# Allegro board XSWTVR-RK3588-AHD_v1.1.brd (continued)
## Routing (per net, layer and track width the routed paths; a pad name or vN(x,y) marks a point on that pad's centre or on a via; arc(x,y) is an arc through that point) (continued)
GMAC1_MDC: length 49.5
  TOP w0.127: v1(112.04,67.83) 112.03,67.84 111.63,67.84 U1.153 ; v1(129.87,77.59) 131.48,77.59 135.1,81.21 135.1,84.49 140.54,89.93 143.28,89.93 143.73,89.48 U19.13
  BOTTOM w0.127: v1(112.04,67.83) 112.04,73.21 113.01,74.18 126.46,74.18 v1(129.87,77.59)
GMAC1_MDIO: length 50.1
  TOP w0.127: U1.152 v1(112.81,66.84) ; U19.14 143.31,89.07 R220.2 142.54,88.87 139.96,88.87 135.45,84.36 135.45,80.98 v1(132.12,77.64)
  BOTTOM w0.127: v1(132.12,77.64) 130.96,77.64 126.75,73.43 113.27,73.43 112.81,72.97 v1(112.81,66.84)
GMAC1_RSTN_L: length 51
  TOP w0.127: R221.1 140.69,90.48 134.77,84.56 134.77,81.37 131.36,77.95 v1(130.76,77.95) ; U1.148 v1(112.44,62.84)
  BOTTOM w0.127: v1(130.76,77.95) 126.6,73.8 113.11,73.8 112.44,73.13 v1(112.44,62.84)
GMAC1_RXCLK: length 43.5
  TOP w0.127: 148.36,79.57 148.19,79.4 v1(146.93,79.4) ; 148.36,79.57 R226.2 ; 148.36,79.57 C304.1 ; v1(113.39,72.56) 112.11,73.84 U1.159
  BOTTOM w0.127: v1(146.93,79.4) 146.93,77.68 146.15,76.89 145.04,76.89 144.86,76.71 131.17,76.71 127.01,72.56 v1(113.39,72.56)
GMAC1_RXD0: length 39.1
  TOP w0.127: v1(146.03,77.38) 146.25,77.59 R222.2 ; U1.160 111.86,74.84 112.71,73.99 112.71,73.99 113.27,73.43 113.27,73.21 v1(113.43,73.06)
  BOTTOM w0.127: v1(113.43,73.06) 126.95,73.06 131.05,77.16 144.68,77.16 144.9,77.38 v1(146.03,77.38)
GMAC1_RXD1: length 39.1
  TOP w0.127: U1.157 112.72,71.84 v1(113.21,71.34) ; R223.2 v1(145.19,76.52)
  BOTTOM w0.127: v1(113.21,71.34) 113.21,71.95 113.45,72.19 127.26,72.19 131.33,76.26 144.93,76.26 v1(145.19,76.52)
GMAC1_RXD2: length 39.1
  TOP w0.127: v1(139.13,77.53) 139.16,77.5 143.53,77.5 R224.2 ; v1(112.75,84.24) 111.15,85.84 U1.171
  BOTTOM w0.127: v1(112.75,84.24) 112.75,81.54 115.93,78.35 125.67,78.35 125.69,78.34 132.67,78.34 133.48,77.53 v1(139.13,77.53)
GMAC1_RXD3: length 40.6
  TOP w0.127: U1.174 111.64,88.84 112.74,87.73 v1(112.74,84.77) ; v1(139.68,77.89) 142.87,77.89 R225.2
  BOTTOM w0.127: v1(139.68,77.89) 133.64,77.89 132.8,78.74 116.24,78.74 113.14,81.84 113.14,84.37 v1(112.74,84.77)
GMAC1_RXDV_CRS: length 42.8
  TOP w0.127: R227.2 v1(147.3,79.91) ; v1(113.59,71.81) 112.56,72.84 U1.158
  BOTTOM w0.127: v1(113.59,71.81) 127.53,71.81 131.5,75.78 145.52,75.78 147.3,77.57 v1(147.3,79.91)
GMAC1_TXCLK: length 55.3
  TOP w0.127: U1.161 111.67,75.84 112.98,74.53 118.63,74.53 119.4,75.3 132.91,75.3 133.83,76.22 134.01,76.22 134.61,75.61 134.79,75.61 134.97,75.79 134.97,75.97 134.37,76.57 134.37,76.75 134.55,76.93 134.73,76.93 135.33,76.33 135.51,76.33 135.69,76.51 135.69,76.69 135.08,77.29 135.08,77.47 135.26,77.65 135.44,77.65 136.05,77.04 136.23,77.04 136.41,77.22 136.41,77.4 135.8,78.01 135.8,78.19 135.98,78.37 136.16,78.37 136.77,77.76 136.95,77.76 137.13,77.94 137.13,78.12 136.52,78.73 136.52,78.91 136.7,79.09 136.88,79.09 137.49,78.48 137.67,78.48 137.85,78.66 137.85,78.84 137.24,79.45 137.24,79.63 137.55,79.94 137.55,81.38 138.06,81.9 138.24,81.9 138.45,81.68 138.63,81.68 138.81,81.86 138.81,82.04 138.6,82.26 138.6,82.44 138.78,82.62 138.96,82.62 139.17,82.4 139.35,82.4 139.53,82.58 139.53,82.76 139.32,82.97 139.32,83.15 139.5,83.33 139.68,83.33 139.89,83.12 140.07,83.12 140.25,83.3 140.25,83.48 140.04,83.69 140.04,83.87 140.22,84.05 140.4,84.05 140.61,83.84 140.79,83.84 140.97,84.02 140.97,84.2 140.75,84.41 140.75,84.59 140.93,84.77 141.11,84.77 141.33,84.56 141.51,84.56 141.69,84.74 141.69,84.92 141.47,85.13 141.47,85.31 C297.1 U19.20
GMAC1_TXD0: length 52.8
  TOP w0.127: v1(114.6,74.91) 117.86,74.91 118.83,75.88 132.46,75.88 136.85,80.28 136.85,82.54 137.64,83.33 137.82,83.33 137.97,83.18 138.15,83.18 138.33,83.36 138.33,83.54 138.18,83.69 138.18,83.87 138.36,84.05 138.54,84.05 138.69,83.9 138.87,83.9 139.05,84.08 139.05,84.26 138.9,84.41 138.9,84.59 139.08,84.77 139.26,84.77 139.41,84.62 139.59,84.62 139.76,84.8 139.76,84.98 139.62,85.13 139.62,85.31 139.8,85.49 139.98,85.49 140.12,85.34 140.3,85.34 140.48,85.52 140.48,85.7 140.34,85.85 140.34,86.03 141.78,87.47 U19.18 ; v1(111.67,65.84) 111.44,65.84 U1.151
  BOTTOM w0.127: v1(114.6,74.91) 112.75,74.91 111.36,73.53 111.36,66.14 v1(111.67,65.84)
GMAC1_TXD1: length 55
  TOP w0.127: v1(114.17,75.28) 117.67,75.28 118.59,76.21 132.31,76.21 136.54,80.44 136.54,82.62 141.8,87.87 U19.17 ; U1.147 111.44,61.84 v1(111.67,61.84)
  BOTTOM w0.127: v1(111.67,61.84) 111.67,65.19 111.02,65.84 111.02,73.72 112.58,75.28 v1(114.17,75.28)
GMAC1_TXD2: length 52.9
  TOP w0.127: U19.16 141.78,88.27 141.34,87.84 141.16,87.84 141,88 140.82,88 140.64,87.82 140.64,87.65 140.8,87.48 140.8,87.3 140.62,87.12 140.44,87.12 140.28,87.29 140.1,87.29 139.92,87.11 139.92,86.93 140.09,86.76 140.09,86.58 139.91,86.4 139.73,86.4 139.56,86.57 139.38,86.57 139.2,86.39 139.2,86.21 139.37,86.04 139.37,85.86 139.19,85.68 139.01,85.68 138.84,85.85 138.66,85.85 138.48,85.67 138.48,85.49 138.65,85.32 138.65,85.14 138.47,84.97 138.29,84.97 138.12,85.13 137.94,85.13 137.76,84.95 137.76,84.77 137.93,84.61 137.93,84.43 137.75,84.25 137.57,84.25 137.41,84.41 137.23,84.41 137.05,84.23 137.05,84.05 137.21,83.89 137.21,83.71 136.19,82.69 136.19,80.68 132.27,76.76 127.72,76.76 v1(127.63,76.85) ; v1(112.35,85.65) 112.35,87 111.51,87.84 U1.173
  BOTTOM w0.127: v1(127.63,76.85) 127.26,77.22 116.63,77.22 112.35,81.5 v1(112.35,85.65)
GMAC1_TXD3: length 52.5
  TOP w0.127: v1(126.91,76.83) 127.3,77.22 127.47,77.22 132.22,77.22 135.78,80.78 135.78,83.44 136.37,84.03 136.37,84.21 136.21,84.37 136.21,84.55 136.39,84.73 136.57,84.73 136.73,84.57 136.91,84.57 137.09,84.75 137.09,84.93 136.93,85.09 136.93,85.27 137.11,85.44 137.28,85.44 137.44,85.28 137.62,85.28 137.8,85.46 137.8,85.64 137.64,85.8 137.64,85.98 137.82,86.16 138,86.16 138.16,86 138.34,86 138.52,86.18 138.52,86.36 138.36,86.52 138.36,86.7 138.54,86.88 138.72,86.88 138.88,86.72 139.06,86.72 139.24,86.9 139.24,87.08 139.08,87.24 139.08,87.42 139.26,87.6 139.44,87.6 139.6,87.44 139.78,87.44 139.96,87.62 139.96,87.8 139.8,87.96 139.8,88.14 139.98,88.32 140.16,88.32 140.32,88.16 140.5,88.16 140.94,88.6 145.38,88.6 U19.15 ; v1(111.98,86.01) 111.98,86.06 111.98,86.06 111.98,86.17 111.31,86.84 U1.172
  BOTTOM w0.127: v1(126.91,76.83) 116.56,76.83 111.98,81.41 v1(111.98,86.01)
GMAC1_TXEN: length 58.8
  TOP w0.127: v1(111.67,56.84) 111.44,56.84 U1.142 ; U19.19 142.03,87.07 140.86,85.9 140.86,85.53 137.16,81.84 137.16,80.08 132.68,75.59 119.12,75.59 118.74,75.21 118.73,75.21 v1(118.47,74.95)
  BOTTOM w0.127: v1(111.67,56.84) 112.03,57.2 112.03,66.18 111.67,66.55 111.67,73.35 112.86,74.55 114.95,74.55 115.36,74.95 v1(118.47,74.95)
GNSS_ANT: length 10
  TOP w0.559: J18.1 80.13,151.41 arc(80.28,150.66) 80.7,150.03 arc(81.35,149.06) 81.58,147.91 L5.1 81.58,143.51 U15.11
GNSS_RST: length 135.2
  TOP w0.127: J24.15 100.89,38.45 101.12,38.68 v1(101.12,39.53) ; U15.8 84.87,144.05 86.19,145.37 92.54,145.37 92.93,144.98 97.08,144.98 97.82,144.23 97.82,114.29 99.22,112.9 102.61,112.9 v1(103.54,111.96)
  L3 w0.127: v1(106.2,104.56) 106.2,106.04 103.54,108.69 v1(103.54,111.96)
  BOTTOM w0.127: v1(106.2,104.56) 106.2,63.38 109.29,60.28 109.29,42.32 107.48,40.5 105.14,40.5 104.17,39.53 v1(101.12,39.53)
GNSS_STATE: length 122.4
  TOP w0.127: v1(104.1,111.96) 102.76,113.3 99.34,113.3 98.23,114.41 98.23,146.55 97.3,147.48 R135.1 ; J24.7 104.89,39.1 104.88,39.1 v1(104.88,39.47)
  L3 w0.127: v1(106.61,103.87) 106.61,106.17 104.1,108.68 v1(104.1,111.96)
  BOTTOM w0.127: v1(106.61,103.87) 106.61,63.57 109.72,60.46 109.72,42.08 107.8,40.16 105.57,40.16 v1(104.88,39.47)
HDMI0_EARC+: length 10.2
  TOP w0.127: J17.14 14.06,88.75 14.07,88.76 ED8.1 14.51,89.05 14.76,89.3 16.02,89.3 16.5,89.77 16.5,90.22 18.04,91.76 C245.2
HDMI0_EARC-: length 12
  TOP w0.127: J17.19 9.54,91.24 13.79,91.24 ED4.1 14.51,92 16.32,93.8 C246.2 16.96,96.99 R121.2
HDMI0_TX0N_PORT: length 8.5
  TOP w0.127: J17.9 9.54,86.24 10.79,86.24 11.17,85.86 12.79,85.86 13.54,85.11 14.1,85.11 14.2,85.21 ED3.9 ED3.2 15.91,85.21 16.01,85.11 17.14,85.11 C240.2
HDMI0_TX0N_PORT/EDP0_TX_D0N: length 30.2
  TOP w0.127: C240.1 18.25,85.36 18.48,85.13 34.72,85.13 41.08,91.49 44.1,91.49 44.45,91.84 U1.16
HDMI0_TX0P_PORT: length 8.5
  TOP w0.127: J17.7 9.54,85.24 10.31,85.24 10.76,85.24 11.08,85.56 12.67,85.56 13.41,84.81 14.12,84.81 14.21,84.71 ED3.10 ED3.1 15.91,84.71 16.01,84.81 17.17,84.81 C239.2
HDMI0_TX0P_PORT/EDP0_TX_D0P: length 30.2
  TOP w0.127: U1.17 44.46,90.84 44.11,91.18 41.21,91.18 34.85,84.82 18.48,84.82 18.25,84.59 C239.1
HDMI0_TX1N_PORT: length 8.5
  TOP w0.127: C238.2 17.17,83.62 15.71,83.62 15.61,83.71 ED2.5 ED2.6 14.22,83.71 14.12,83.62 13.33,83.62 12.56,84.39 11.13,84.39 10.79,84.74 9.54,84.74 J17.6
HDMI0_TX1N_PORT/EDP0_TX_D1N: length 30.6
  TOP w0.127: U1.18 44.56,89.84 44.21,89.49 41.24,89.49 35.36,83.6 28.07,83.6 27.81,83.86 27.18,83.86 26.92,83.6 26.45,83.6 26.19,83.86 25.55,83.86 25.3,83.6 24.82,83.6 24.56,83.86 23.93,83.86 23.67,83.6 18.48,83.6 18.25,83.83 C238.1
HDMI0_TX1P_PORT: length 8.5
  TOP w0.127: C237.2 17.14,83.31 15.71,83.31 15.61,83.21 ED2.4 ED2.7 14.24,83.21 14.15,83.31 13.21,83.31 12.43,84.09 11.14,84.09 10.79,83.74 9.54,83.74 J17.4
HDMI0_TX1P_PORT/EDP0_TX_D1P: length 30.6
  TOP w0.127: U1.19 44.59,88.84 44.24,89.18 41.37,89.18 35.48,83.3 27.95,83.3 27.69,83.56 27.31,83.56 27.05,83.3 26.32,83.3 26.06,83.56 25.68,83.56 25.42,83.3 24.7,83.3 24.44,83.56 24.06,83.56 23.8,83.3 18.48,83.3 18.25,83.07 C237.1
HDMI0_TX2N_PORT: length 8.5
  TOP w0.127: C236.2 17.19,82.12 15.72,82.12 15.62,82.22 ED2.2 ED2.9 14.19,82.22 14.09,82.11 13.24,82.11 13.15,82.2 12.97,82.38 12.46,82.89 11.13,82.89 10.78,83.24 9.54,83.24 J17.3
HDMI0_TX2N_PORT/EDP0_TX_D2N: length 30.6
  TOP w0.127: C236.1 18.25,82.31 18.48,82.08 19.59,82.08 19.71,82.21 19.71,82.22 20.02,82.52 20.53,82.52 20.83,82.22 20.83,82.21 20.96,82.08 21.21,82.08 21.34,82.21 21.34,82.22 21.65,82.52 22.15,82.52 22.46,82.22 22.46,82.21 22.59,82.08 35.99,82.08 41.4,87.49 44.26,87.49 44.61,87.84 U1.20
HDMI0_TX2P_PORT: length 8.5
  TOP w0.127: C235.2 17.12,81.81 15.68,81.81 15.58,81.72 ED2.1 ED2.10 14.17,81.72 14.08,81.81 13.11,81.81 12.84,82.08 12.75,82.16 12.33,82.59 11.1,82.59 10.76,82.25 J17.1
HDMI0_TX2P_PORT/EDP0_TX_D2P: length 30.6
  TOP w0.127: U1.21 44.64,86.84 44.3,87.18 41.52,87.18 36.11,81.78 22.46,81.78 22.15,82.08 22.15,82.09 22.03,82.22 21.77,82.22 21.65,82.09 21.65,82.08 21.34,81.78 20.83,81.78 20.53,82.08 20.53,82.09 20.4,82.22 20.15,82.22 20.02,82.09 20.02,82.08 19.71,81.78 18.48,81.78 18.25,81.55 C235.1
HDMI0_TX3N_PORT: length 8.5
  TOP w0.127: J17.12 9.54,87.74 10.31,87.74 10.79,87.74 11.14,87.39 13.01,87.39 13.79,86.61 14.1,86.61 14.19,86.71 ED3.6 ED3.5 15.91,86.71 16.01,86.61 17.12,86.61 C242.2
HDMI0_TX3N_PORT/EDP0_TX_D3N: length 30.4
  TOP w0.127: U1.14 44.43,93.84 44.08,93.49 39.67,93.49 32.83,86.65 18.48,86.65 18.25,86.88 C242.1
HDMI0_TX3P_PORT: length 8.5
  TOP w0.127: J17.10 9.54,86.74 10.31,86.74 10.76,86.74 11.1,87.09 12.88,87.09 13.66,86.31 14.09,86.31 14.19,86.21 ED3.7 ED3.4 15.91,86.21 16.01,86.31 17.19,86.31 C241.2
HDMI0_TX3P_PORT/EDP0_TX_D3P: length 30.4
  TOP w0.127: U1.15 44.39,92.84 44.04,93.18 39.8,93.18 32.96,86.35 18.48,86.35 18.25,86.12 C241.1
HDMI0_TX_CEC_PORT: length 10.8
  TOP w0.127: J17.13 10.3,88.25 10.31,88.24 13.97,88.24 ED7.1 14.51,87.89 14.81,88.19 16.63,88.19 Q9.3 17.9,89.47 R118.2
HDMI0_TX_SBDN/EDP0_TX_AUXN: length 31.5
  TOP w0.127: U1.12 35.67,95.84 32.46,99.04 24.42,99.04 24.37,99.09 16.96,99.09 16.32,98.45 C246.1
HDMI0_TX_SBDP/EDP0_TX_AUXP: length 28
  TOP w0.127: C245.1 18.76,91.63 35.64,91.63 38.85,94.84 U1.13
HDMI0_TX_SCL_PORT: length 11.6
  TOP w0.127: Q7.3 18.3,92.86 R113.2 15.8,90.35 14.69,90.35 14.51,90.18 ED6.1 14.51,89.78 13.99,89.25 J17.15
HDMI0_TX_SDA_PORT: length 13.7
  TOP w0.127: Q8.3 18.49,95.4 R116.2 17.13,94.72 17.13,92.8 15.74,91.42 14.93,91.42 14.51,91 ED5.1 14.51,90.84 13.42,89.75 J17.16
HDMITX0_CEC_M0: length 125.9
  TOP w0.127: v1(23.6,88.84) 21.82,88.84 21.18,89.47 R117.2 21.09,89.46 Q9.2 ; U1.170 109.1,84.84 v1(109.06,84.84)
  L3 w0.127: v1(59.59,109.13) 57.07,109.13 55.46,110.75 50.14,110.75 38.46,99.07 29.95,99.07 24.44,93.56 24.44,89.3 23.97,88.84 v1(23.6,88.84)
  BOTTOM w0.127: v1(109.06,84.84) 108.87,85.02 108.87,104.68 106.32,107.23 60.42,107.23 59.59,108.06 v1(59.59,109.13)
HDMITX0_HPDIN: length 53.9
  TOP w0.127: U1.231 71.31,109.44 70.94,109.8 62,109.8 61.38,110.43 v1(61.38,110.78) ; Q10.3 26.42,97.85 R119.1 v1(27.7,98.35)
  L3 w0.127: v1(27.7,98.35) 29.4,100.05 38,100.05 49.58,111.63 56.2,111.63 57.05,110.78 v1(61.38,110.78)
HDMITX0_SCL_M0: length 123
  TOP w0.127: U1.168 v1(109.03,82.84) ; Q7.2 22.64,93.51 R112.2 v1(23.46,93.36)
  L3 w0.127: v1(60.27,110.01) 59.79,109.53 57.23,109.53 55.73,111.03 49.93,111.03 38.3,99.4 29.75,99.4 23.97,93.62 23.72,93.62 v1(23.46,93.36)
  BOTTOM w0.127: v1(60.27,110.01) 60.3,109.98 60.3,108.14 60.96,107.48 106.75,107.48 109.27,104.97 109.27,85.24 109.43,85.08 109.43,83.23 v1(109.03,82.84)
HDMITX0_SDA_M0: length 119.7
  TOP w0.127: Q8.2 22.54,96.05 C243.2 23.7,95.79 R114.2 23.79,95.85 24.35,96.41 v1(25.71,96.41) ; U1.169 v1(109.03,83.84)
  L3 w0.127: v1(25.71,96.41) 26.29,96.41 29.58,99.7 38.12,99.7 49.77,111.34 55.93,111.34 57.37,109.91 v1(58.66,109.91)
  BOTTOM w0.127: v1(58.66,109.91) 58.66,108.15 59.83,106.97 105.85,106.97 108.49,104.34 108.49,84.34 108.99,83.84 v1(109.03,83.84)
HOST_WAKE_BT_H: length 40.8
  TOP w0.127: U14.49 76.79,143.22 78.67,141.35 78.67,113.83 79.9,112.6 83.07,112.6 84.31,111.36 U1.218
I2C4_SCL_M1_GPIO2-B5: length 119.7
  TOP w0.127: U1.211 91.31,106.56 v1(91.31,106.56)
  L3 w0.127: 91.31,106.59 v1(91.31,106.56) 90.56,107.31 88.43,107.31 88.08,106.96 49.42,106.96 42.66,100.19 42.66,55.11 39.56,52.01 39.56,51.82 36.81,49.06 36.61,49.06 v1(28.55,41)
  BOTTOM w0.127: J2.25 v1(28.55,41)
I2C4_SDA_M1_GPIO2-B4: length 105.9
  TOP w0.127: U1.212 v1(90.31,106.56)
  L3 w0.127: v1(90.31,106.56) 89.99,106.88 88.53,106.88 88.26,106.6 49.58,106.6 43.08,100.1 43.08,54.98 40.19,52.09 40.19,51.88 v1(39.93,51.62)
  BOTTOM w0.127: J2.68 39.3,50.99 v1(39.93,51.62)
I2C_ADDR_CE: length 2.2
  TOP w0.127: U23.26 51.22,116.97 52.18,116.01 R267.1
I2S0_LRCK_TX: length 50.5
  TOP w0.127: R263.1 v1(46.67,121.64) ; U1.220 82.31,111.54 v1(82.31,111.54)
  BOTTOM w0.127: v1(46.67,121.64) 48,120.31 51.44,120.31 54.3,123.17 60.13,123.17 62.24,121.07 62.24,114.27 64.01,112.5 79.46,112.5 80.41,111.54 v1(82.31,111.54)
I2S0_MCLK: length 44.6
  TOP w0.127: U1.222 80.31,108.77 80.73,109.19 v1(80.73,111.96) ; v1(51.19,120.7) 50.89,121 R260.1
  BOTTOM w0.127: v1(80.73,111.96) 79.79,112.9 64.22,112.9 62.56,114.55 62.56,121.38 60.34,123.6 54.08,123.6 v1(51.19,120.7)
I2S0_SCLK_TX: length 49.6
  TOP w0.127: R261.1 v1(48.7,121.64) ; U1.219 v1(83.31,111.76)
  BOTTOM w0.127: v1(83.31,111.76) 81.5,113.56 64.91,113.56 63.29,115.18 63.29,122.01 60.83,124.47 53.7,124.47 50.88,121.64 v1(48.7,121.64)
I2S0_SDI0: length 33.1
  TOP w0.127: R264.1 v1(45.65,121.64) ; U1.239 v1(63.31,109.3)
  BOTTOM w0.127: v1(45.65,121.64) 47.36,119.93 51.72,119.93 54.53,122.74 59.94,122.74 61.86,120.82 61.86,114 63.31,112.55 v1(63.31,109.3)
I2S0_SDO0: length 48.8
  TOP w0.127: R262.1 v1(47.68,121.64) ; U1.221 v1(81.31,111.97)
  BOTTOM w0.127: v1(81.31,111.97) 80.04,113.24 64.55,113.24 62.9,114.89 62.9,121.75 60.58,124.07 53.8,124.07 50.86,121.14 48.18,121.14 v1(47.68,121.64)
INPUT1: length 125.6
  TOP w0.127: v1(37.57,123.96) ED40.1 37,124.4 36.8,124.6 36.8,131.8 U24.E2
  BOTTOM w0.127: v1(37.57,123.96) 38.21,123.31 40.18,123.31 44.17,119.33 44.17,96.7 47.42,93.45 47.42,60.41 48.54,59.3 54.94,59.3 64.71,49.53 64.71,41.04 65.88,39.86 75,39.86 75.53,39.34 78.23,39.34 D33.1 79.59,38.99 R280.1
INPUT2: length 115.7
  TOP w0.127: U24.F2 34.32,131.78 34.32,126.33 35.82,124.83 ED37.1 v1(36.39,123.96)
  BOTTOM w0.127: R278.1 67.76,39.11 D34.1 66.01,39.11 64.39,40.73 64.39,49.48 54.83,59.04 48.43,59.04 47.16,60.31 47.16,93.32 43.92,96.56 43.92,119.01 40.39,122.54 37.45,122.54 36.39,123.6 v1(36.39,123.96)
INPUT3: length 132.2
  TOP w0.127: U24.G2 33.98,129.62 33.98,125.4 34.59,124.79 ED34.1 v1(35.16,123.96)
  BOTTOM w0.127: 78.58,34.58 D35.1 ; D35.1 79.6,34.55 R279.1 ; D35.1 78.31,34.81 74.65,34.81 74.3,35.16 67.06,35.16 63.36,38.86 63.36,49.11 54.26,58.21 48.09,58.21 46.34,59.96 46.34,92.9 43.1,96.15 43.1,96.16 43.09,96.17 43.09,118.27 39.6,121.76 39.3,121.76 36.33,121.76 35.16,122.93 v1(35.16,123.96)
INPUT4: length 123.2
  TOP w0.127: v1(31.55,123.95) ED31.1 30.98,124.98 29.26,126.7 29.26,131.83 U24.H2
  BOTTOM w0.127: v1(31.55,123.95) 31.55,123.56 34.24,120.87 39.23,120.87 42.26,117.84 42.26,101.54 42.26,101.37 42.26,95.82 45.52,92.56 45.52,59.62 47.78,57.36 53.72,57.36 62.44,48.64 62.44,38.09 63.88,36.65 64.41,36.65 66.59,34.47 D36.1 67.13,34.47 67.28,34.62 R281.1
LAN0_A+: length 22.7
  TOP w0.127: J28.1 114.22,129.87 114.37,130.03 116.05,130.03 116.78,129.3 116.78,120.83 118.55,119.06 118.55,118.88 118.45,118.78 118.45,118.6 118.63,118.42 118.8,118.42 118.91,118.52 119.09,118.52 120.03,117.58 120.03,113.65 119.54,113.17 U16.23
LAN0_A-: length 22.6
  TOP w0.127: J28.2 114.22,130.48 114.36,130.33 116.18,130.33 117.09,129.43 117.09,120.96 120.33,117.71 120.33,113.68 120.81,113.2 U16.22
LAN0_B+: length 36.4
  TOP w0.127: J28.3 110.72,128.87 110.56,129.02 110.56,132.41 111.34,133.19 117.43,133.19 118.93,131.69 118.93,123.35 119.41,122.87 119.41,122.53 119.6,122.34 119.94,122.34 120.13,122.15 120.13,121.81 120.32,121.62 120.66,121.62 120.85,121.43 120.85,121.1 121.04,120.91 121.38,120.91 121.57,120.72 121.57,120.38 121.76,120.19 122.1,120.19 122.29,120 122.29,119.66 122.48,119.47 122.82,119.47 123.01,119.28 123.01,118.94 123.2,118.75 123.53,118.75 123.84,118.45 123.84,113.74 123.35,113.25 U16.20
LAN0_B-: length 36.4
  TOP w0.127: J28.6 109.14,130.21 109.33,130.02 110.13,130.02 110.26,130.14 110.26,132.54 111.21,133.49 117.56,133.49 119.24,131.81 119.24,123.48 124.14,118.58 124.14,113.67 124.62,113.19 U16.19
LAN0_C+: length 38.9
  TOP w0.127: U16.17 127.17,113.2 127.66,113.69 127.66,115.49 v1(127.43,115.71)
  BOTTOM w0.127: J28.4 111.68,130.97 111.2,130.49 110.73,130.49 110.44,130.78 110.44,132.21 111.09,132.86 120.32,132.86 121.21,131.98 121.21,123.3 122.58,121.93 122.58,121.75 122.57,121.74 122.57,121.56 122.75,121.38 122.93,121.38 122.94,121.39 123.12,121.39 123.3,121.21 123.3,121.03 123.29,121.02 123.29,120.84 123.47,120.66 123.65,120.66 123.66,120.67 123.84,120.67 124.02,120.49 124.02,120.31 124.01,120.3 124.01,120.12 124.19,119.94 124.37,119.94 124.38,119.95 124.56,119.95 124.74,119.77 124.74,119.59 124.73,119.58 124.73,119.4 124.91,119.23 125.09,119.23 125.09,119.23 125.27,119.23 125.45,119.05 125.45,118.87 125.45,118.87 125.45,118.69 125.63,118.51 125.81,118.51 125.81,118.51 125.99,118.51 126.17,118.33 126.17,118.15 126.17,118.15 126.17,117.97 126.35,117.79 126.52,117.79 126.53,117.8 126.71,117.8 126.89,117.62 126.89,117.44 126.88,117.43 126.88,117.25 127.06,117.07 127.24,117.07 127.25,117.08 127.43,117.08 127.66,116.85 127.66,115.94 v1(127.43,115.71)
LAN0_C-: length 38.9
  TOP w0.127: U16.16 128.44,113.21 127.96,113.69 127.96,115.49 v1(128.19,115.71)
  BOTTOM w0.127: J28.5 109.62,128.87 110.14,129.38 110.14,132.34 110.96,133.17 120.45,133.17 121.51,132.1 121.51,123.43 127.96,116.98 127.96,115.94 v1(128.19,115.71)
LAN0_D+: length 46.9
  TOP w0.127: J28.7 106.6,129.83 106.81,130.04 107.64,130.04 108.01,130.41 108.01,133.5 109.61,135.1 121,135.1 121.85,134.25 121.85,128 126.41,123.45 126.41,123.26 126.68,122.99 126.86,122.99 127.13,122.73 127.13,122.54 127.39,122.27 127.58,122.27 127.85,122.01 127.85,121.82 128.11,121.55 128.3,121.55 128.57,121.29 128.57,121.1 128.77,120.9 128.95,120.9 131.47,118.39 131.47,113.71 130.98,113.22 U16.14
LAN0_D-: length 46.8
  TOP w0.127: J28.8 106.6,130.56 106.81,130.35 107.51,130.35 107.7,130.54 107.7,133.63 109.48,135.41 121.13,135.41 122.16,134.37 122.16,128.13 131.77,118.52 131.77,113.7 132.25,113.22 U16.13
LAN0_MCT1: length 3
  TOP w0.508: U16.24 v1(118.27,110.9)
  BOTTOM w0.508: R153.1 v1(118.27,110.9)
LAN0_MCT2: length 3
  TOP w0.508: U16.21 v1(122.08,110.9)
  BOTTOM w0.508: R152.1 v1(122.08,110.9)
LAN0_MCT3: length 3
  TOP w0.508: U16.18 v1(125.9,110.9)
  BOTTOM w0.508: R151.1 v1(125.9,110.9)
LAN0_MCT4: length 3
  TOP w0.508: U16.15 v1(129.71,110.9)
  BOTTOM w0.508: R150.1 v1(129.71,110.9)
LAN1_A+: length 22.8
  TOP w0.127: J27.1 145.6,129.72 145.86,129.98 146.96,129.98 147.3,129.65 147.3,126.85 145.71,125.25 145.71,118.1 145.51,117.91 145.28,117.91 145.04,117.67 145.04,117.43 144.79,117.19 144.56,117.19 144.32,116.95 144.32,116.71 144.08,116.47 143.84,116.47 143.6,116.23 143.6,115.99 143.36,115.75 143.12,115.75 142.88,115.51 142.88,115.28 141.92,114.31 141.92,113.74 141.43,113.25 U18.23
LAN1_A-: length 22.8
  TOP w0.127: J27.2 145.6,130.56 145.87,130.29 147.09,130.29 147.61,129.77 147.61,126.72 146.01,125.13 146.01,117.98 142.22,114.19 142.22,113.73 142.7,113.24 U18.22
LAN1_B+: length 36.9
  TOP w0.127: U18.20 145.24,113.26 145.73,113.74 145.73,115.04 145.96,115.28 145.96,115.46 145.93,115.5 145.93,115.68 146.11,115.85 146.29,115.85 146.32,115.82 146.5,115.82 146.68,116 146.68,116.18 146.65,116.21 146.65,116.39 146.83,116.57 147.01,116.57 147.04,116.54 147.22,116.54 147.74,117.06 147.74,118.36 147.59,118.52 147.59,118.87 147.74,119.03 147.74,119.38 147.59,119.53 147.59,119.89 147.74,120.04 147.74,120.39 147.59,120.55 147.59,120.9 147.74,121.06 147.74,121.41 147.59,121.57 147.59,121.92 147.74,122.07 147.74,125.07 151,128.32 151,131.97 149.99,132.98 142.83,132.98 141.85,131.99 141.85,129.31 142.29,128.87 J27.3
LAN1_B-: length 36.9
  TOP w0.127: U18.19 146.51,113.3 146.03,113.78 146.03,114.92 148.05,116.94 148.05,124.94 151.31,128.2 151.31,132.1 150.12,133.28 142.71,133.28 141.54,132.12 141.54,130.22 141.29,129.96 140.76,129.96 140.52,130.2 J27.6
LAN1_C+: length 32.7
  TOP w0.127: v1(149.32,115.25) 149.55,115.02 149.55,113.66 149.06,113.18 U18.17
  BOTTOM w0.127: J27.4 143.06,130.88 142.65,130.47 142.07,130.47 141.89,130.65 141.89,132.2 142.48,132.79 148.56,132.79 149.07,132.29 149.07,122.58 149.55,122.1 149.55,121.26 149.42,121.13 149.39,121.13 149.27,121 149.27,120.75 149.39,120.62 149.42,120.62 149.55,120.5 149.55,120.24 149.42,120.12 149.39,120.12 149.27,119.99 149.27,119.73 149.39,119.61 149.42,119.61 149.55,119.48 149.55,119.23 149.42,119.1 149.39,119.1 149.27,118.97 149.27,118.72 149.39,118.59 149.42,118.59 149.55,118.46 149.55,118.21 149.42,118.08 149.39,118.08 149.27,117.96 149.27,117.7 149.39,117.58 149.42,117.58 149.55,117.45 149.55,117.19 149.42,117.07 149.39,117.07 149.27,116.94 149.27,116.69 149.39,116.56 149.42,116.56 149.55,116.43 149.55,115.47 v1(149.32,115.25)
LAN1_C-: length 32.7
  TOP w0.127: U18.16 150.33,113.27 149.85,113.75 149.85,115.02 v1(150.08,115.25)
  BOTTOM w0.127: v1(150.08,115.25) 149.85,115.47 149.85,122.23 149.37,122.71 149.37,132.41 148.69,133.1 142.35,133.1 141.58,132.32 141.58,129.92 J27.5
LAN1_D+: length 42
  TOP w0.127: J27.7 137.98,129.76 138.33,130.1 139.08,130.1 139.39,130.41 139.39,133.81 140.18,134.6 152.51,134.6 153.35,133.76 153.35,113.74 152.87,113.26 U18.14
LAN1_D-: length 42
  TOP w0.127: U18.13 154.14,113.24 153.66,113.72 153.66,133.88 152.64,134.9 140.05,134.9 139.08,133.93 139.08,130.54 138.95,130.41 138.77,130.41 138.61,130.56 138.61,130.78 J27.8
LAN1_MCT1: length 3
  TOP w0.508: U18.24 v1(140.16,110.93)
  BOTTOM w0.508: R197.1 v1(140.16,110.93)
LAN1_MCT2: length 3
  TOP w0.508: U18.21 v1(143.97,110.93)
  BOTTOM w0.508: R196.1 v1(143.97,110.93)
LAN1_MCT3: length 3
  TOP w0.508: U18.18 v1(147.79,110.93)
  BOTTOM w0.508: R195.1 v1(147.79,110.93)
LAN1_MCT4: length 3
  TOP w0.508: U18.15 v1(151.6,110.93)
  BOTTOM w0.508: R194.1 v1(151.6,110.93)
LINE_OUT_L: length 42.5
  TOP w0.254: 40.73,123.97 40.95,123.97 41.37,123.54 41.37,122.69 R268.2 ; 40.73,123.97 41.38,124.62 41.38,138.29 40.9,138.77 24.39,138.77 23.88,139.28 23.88,142.09 24.43,142.64 26.45,142.64 U24.H4 ; 40.73,123.97 ED30.1
LINE_OUT_R: length 37.2
  TOP w0.254: R269.2 41.75,122.64 41.75,123.54 42.19,123.98 42.31,123.98 ; 42.31,123.98 42.31,123.98 ED29.1 ; 42.31,123.98 42.31,124.03 41.76,124.57 41.76,138.45 40.98,139.22 24.52,139.22 24.26,139.48 24.26,140.22 U24.J4
LMIC_CP: length 45.7
  TOP w0.203: C326.1 R258.1 C330.1 C327.1 56.01,115.12 56.01,120.55 54.01,122.55 46.68,122.55 46.4,122.82 46.4,123.52 45.95,123.97 ED39.1 45.81,124.64 44.23,126.22 44.23,138.01 42.26,139.99 36.61,139.99 U24.E4
MCU_3V3: length 109.8
  TOP w0.254: U8.1 108.89,20.03 v1(108.87,20.03) ; v1(97.37,20.03) 97.39,20.03 U8.48 ; U8.19 v1(107.17,30.84) ; U8.64 108.17,16.75 ; 108.17,16.75 v1(108.17,16.73) 108.17,16.75 ; U8.32 v1(100.67,30.84)
  TOP w0.305: C72.1 109.29,31.09 F1.1 ; C72.1 109.32,31.13 C71.1 ; C72.1 108.3,31.12 108.02,30.84 v1(107.17,30.84)
  TOP w0.381: U9.5 73.93,27.35 74.3,26.98 v1(76.16,26.98) ; v2(109.73,11.55) R27.1 108.96,11.6 C46.1 ; U10.5 86.53,27.46 C368.2 v1(88.44,26.86) 89.17,26.86 90.39,25.64 90.39,23.8 93.64,20.55 J1.1 ; R346.1 95.61,32.73 C377.1 95.94,32.63 v2(96.45,33.13) ; U6.6 106,14.57 C51.1 106.99,14.59 C52.2 107,15.29 107.4,15.7 C76.2 108.92,15.7 Q31.2 ; R341.1 v2(113.05,16.61)
  TOP w0.508: 107.16,30.85 v1(107.17,30.84) ; v2(109.14,17.37) v2(109.14,16.64) Q31.2
  BOTTOM w0.381: v1(108.87,20.03) C67.1 ; C67.1 109.59,17.83 v2(109.14,17.37) ; C67.1 109.59,29.32 108.85,30.07 C70.1 ; v1(100.67,30.84) 100.62,30.78 C66.1 ; C70.1 100.67,30.07 C66.1 ; C70.1 107.15,30.81 v1(107.17,30.84) ; J1.1 93.64,20.1 95.14,21.6 95.14,23.11 96.03,24.01 98.22,24.01 ; C66.1 98.62,30.12 98.21,29.71 98.22,29.7 98.22,24.01 ; v2(109.14,17.37) 109.14,16.64 v2(109.14,16.64) 109.73,16.05 v2(109.73,11.55) ; v2(109.14,17.37) 112.29,17.37 v2(113.05,16.61) ; C68.1 108.16,16.74 v1(108.17,16.73) ; 98.22,24.01 98.22,20 98.21,19.99 ; v1(76.16,26.98) 76.61,26.53 88.11,26.53 v1(88.44,26.86) ; C69.1 98.21,19.99 ; 98.21,19.99 98.17,20.03 v1(97.37,20.03)
  BOTTOM w0.508: C68.1 108.18,17.37 v2(109.14,17.37) ; v2(96.45,33.13) 96.94,32.65 96.94,30.98 98.21,29.71
MCU_CAN0_EN: length 30
  TOP w0.127: U8.38 97.48,25.03 95.47,27.04 95.47,28.29 94.05,29.71 91.04,29.71 90.15,30.61 76.45,30.61 76.23,30.39 76.23,29.98 76.32,29.89 76.32,28.95 75.99,28.62 U9.6
MCU_CAN0_H: length 125
  TOP w0.127: R44.1 63.58,24.13 63.58,37.37 v1(63.92,37.71) ; U24.F1 32.82,125.3 33.4,124.72 ED38.1 v1(33.97,123.95)
  BOTTOM w0.127: v1(33.97,123.95) 34.41,123.51 34.41,122.57 35.51,121.47 39.43,121.47 42.83,118.07 42.83,96.03 46.08,92.78 46.08,59.86 48,57.95 54.09,57.95 63.02,49.01 63.02,38.61 63.89,37.75 63.89,37.74 v1(63.92,37.71)
MCU_CAN0_L: length 124.9
  TOP w0.127: v1(64.05,37.05) 64.05,37.05 R45.1 ; U24.G1 30.32,126.81 32.21,124.92 ED35.1 v1(32.78,123.95)
  BOTTOM w0.127: v1(32.78,123.95) 32.78,123.5 35.09,121.18 39.28,121.18 42.52,117.95 42.52,101.54 42.51,101.37 42.51,95.93 45.78,92.67 45.78,59.74 47.9,57.62 53.94,57.62 62.72,48.84 62.72,38.38 v1(64.05,37.05)
MCU_CAN0_NSTB: length 41.3
  TOP w0.127: U8.36 97.48,26.03 96.13,27.39 96.13,28.67 94.38,30.41 91.22,30.41 90.51,31.12 70.78,31.12 69.71,30.05 69.71,23.49 68.49,22.27 U9.14
MCU_CAN1_EN: length 14.3
  TOP w0.127: U10.6 86.79,28.75 87.48,28.06 90.72,28.06 92.29,26.48 94.48,26.48 97.43,23.53 U8.41
MCU_CAN1_H: length 139.6
  TOP w0.127: v1(29.16,123.95) ED32.1 28.6,124.93 27.82,125.71 U24.H1 ; R332.1 76.59,24.29 76.59,30.23 v1(76.6,30.24)
  BOTTOM w0.127: v1(76.6,30.24) 75.95,30.89 72.45,30.89 71.38,31.96 66.12,31.96 62.15,35.93 62.15,48.41 53.47,57.09 45.51,57.09 40.11,62.48 40.11,118.78 38.67,120.22 32.44,120.22 29.16,123.49 v1(29.16,123.95)
MCU_CAN1_L: length 141.4
  TOP w0.127: v1(27.98,123.96) ED27.1 27.41,125.06 25.32,127.15 U24.J1 ; R334.1 77.09,24.92 v1(77.09,30.24)
  BOTTOM w0.127: v1(77.09,30.24) 77.09,30.15 76.78,29.84 76.42,29.84 75.66,30.6 71.9,30.6 70.82,31.68 65.84,31.68 61.8,35.72 61.8,48.21 53.2,56.81 45.33,56.81 39.58,62.56 39.58,118.83 38.5,119.9 32.03,119.9 29.45,122.48 28.38,122.48 27.98,122.88 v1(27.98,123.96)
MCU_CAN1_NSTB: length 26.2
  TOP w0.127: U10.14 81.04,22.4 82.7,24.06 82.7,28.3 83.8,29.4 87.17,29.4 87.97,28.6 94.2,28.6 94.83,27.97 94.83,26.69 97.48,24.03 U8.40
MCU_DEBUG_RX: length 20.2
  TOP w0.127: U25.9 87.78,11.83 91.95,16.01 96.34,16.01 v1(96.86,16.53) ; U8.43 v1(96.85,22.53)
  BOTTOM w0.127: v1(96.86,16.53) 96.86,22.53 v1(96.85,22.53)
MCU_DEBUG_RX1: length 163.5
  TOP w0.127: U24.B2 43.81,132.29 43.81,125.88 44.61,125.09 ED48.1 45.21,123.97 v1(45.21,123.97) ; R309.2 77.42,12.41 72.5,12.41 70.32,14.59 70.32,16.86 J23.2 70.23,19.03 70.23,19.77 69.68,20.32 65.43,20.32 62.81,22.94 62.81,38.35 v1(64.21,39.75)
  BOTTOM w0.127: v1(45.21,123.97) 44.67,123.97 43.97,124.67 36.01,124.67 35.64,124.3 35.64,122.95 36.57,122.01 39.4,122.01 39.87,122.01 43.34,118.54 43.34,96.27 46.6,93.02 46.6,60.07 48.2,58.47 54.47,58.47 63.68,49.26 63.68,40.28 v1(64.21,39.75)
MCU_DEBUG_TX: length 20.1
  TOP w0.127: v1(96.2,16.53) 91.47,16.53 88.03,13.1 U25.10 ; U8.42 v1(96.19,23.03)
  BOTTOM w0.127: v1(96.2,16.53) 96.2,23.03 v1(96.19,23.03)
MCU_DEBUG_TX1: length 156.4
  TOP w0.127: R308.2 77.46,12.67 72.66,12.67 70.58,14.75 70.58,16.88 J23.3 70.55,19.13 70.55,19.93 69.85,20.62 65.65,20.62 63.1,23.18 63.1,37.85 v1(64.6,39.35) ; U24.B1 42.82,125.7 43.42,125.1 ED47.1 v1(43.99,123.97)
  BOTTOM w0.127: v1(64.6,39.35) 64.6,39.96 64.08,40.48 64.08,49.4 54.69,58.79 48.33,58.79 46.89,60.22 46.89,93.16 43.66,96.39 43.66,118.73 40.12,122.27 39.51,122.27 37.37,122.27 36.02,123.61 36.02,124.24 36.16,124.38 43.58,124.38 v1(43.99,123.97)
MCU_RST: length 14.8
  TOP w0.127: K1.2 115.75,31.77 C62.1 113.81,29.93 R36.2 112.82,29.93 112.17,29.28 110.4,29.28 108.83,27.71 108.83,23.49 109.3,23.03 U8.7
MCU_WAKEUP_RK3588: length 12
  TOP w0.127: U8.44 99.52,22.03 99.76,22.27 99.79,22.27 100.05,22.54 100.05,30.01 99.57,30.48 Q33.2
MIPI_CSI0_RX_CLK0N: length 27.4
  TOP w0.127: U11.85 127.56,35.79 127.51,35.83 127.51,40.75 125.59,42.67 119.3,42.67 112.91,49.06 112.91,49.83 112.25,50.5 111.48,50.5 111.14,50.84 U1.136
MIPI_CSI0_RX_CLK0P: length 27.4
  TOP w0.127: U11.86 127.16,35.81 127.2,35.86 127.2,40.63 125.46,42.37 119.18,42.37 117.42,44.13 117.23,44.13 116.96,44.39 116.96,44.58 116.7,44.85 116.51,44.85 116.25,45.11 116.25,45.3 115.98,45.57 115.79,45.57 115.53,45.83 115.53,46.02 115.26,46.28 115.07,46.28 114.81,46.55 114.81,46.74 112.61,48.94 112.61,49.71 112.12,50.19 111.38,50.19 111.02,49.84 U1.135
MIPI_CSI0_RX_D0N: length 32.4
  TOP w0.127: U1.140 111.07,54.84 111.42,54.49 112.77,54.49 115.05,52.2 115.05,49.89 120.37,44.57 126.72,44.57 129.13,42.17 129.13,35.14 U11.81
MIPI_CSI0_RX_D0P: length 32.5
  TOP w0.127: U1.139 111.06,53.84 111.41,54.18 112.64,54.18 114.75,52.08 114.75,49.77 116.94,47.57 116.94,47.35 117.19,47.1 117.41,47.1 117.66,46.85 117.66,46.63 117.91,46.38 118.13,46.38 118.38,46.13 118.38,45.92 118.63,45.67 118.85,45.67 119.1,45.42 119.1,45.2 119.35,44.95 119.56,44.95 120.24,44.27 126.6,44.27 128.82,42.04 128.82,35.18 U11.82
MIPI_CSI0_RX_D1N: length 29.9
  TOP w0.127: U11.83 128.36,35.79 128.31,35.83 128.31,41.48 126.26,43.53 119.94,43.53 114,49.46 114,50.89 112.41,52.49 111.54,52.49 111.19,52.84 U1.138
MIPI_CSI0_RX_D1P: length 29.8
  TOP w0.127: U1.137 111.13,51.84 111.47,52.18 112.28,52.18 113.7,50.77 113.7,49.34 116.68,46.36 116.68,46.14 116.92,45.89 117.15,45.89 117.39,45.64 117.39,45.42 117.64,45.17 117.86,45.17 118.11,44.92 118.11,44.7 118.36,44.45 118.58,44.45 119.81,43.22 126.14,43.22 128,41.36 128,35.86 127.96,35.82 U11.84
MIPI_CSI0_RX_D2N: length 26.2
  TOP w0.127: U1.134 111.04,48.84 111.38,48.49 111.87,48.49 113.33,47.03 113.33,46.5 113.55,46.28 114.08,46.28 114.48,45.88 114.48,45.35 114.7,45.13 115.23,45.13 115.63,44.73 115.63,44.2 115.85,43.98 116.38,43.98 116.78,43.58 116.78,43.05 117,42.83 117.53,42.83 118.53,41.83 124.92,41.83 126.71,40.04 126.71,40 126.71,39.44 126.71,39.44 126.71,35.82 126.76,35.78 U11.87
MIPI_CSI0_RX_D2P: length 26.3
  TOP w0.127: U11.88 126.36,35.8 126.4,35.84 126.4,39.92 124.8,41.52 123.77,41.52 123.63,41.38 123.26,41.38 123.13,41.52 122.76,41.52 122.62,41.38 122.25,41.38 122.11,41.52 121.74,41.52 121.6,41.38 121.23,41.38 121.09,41.52 120.72,41.52 120.59,41.38 120.22,41.38 120.08,41.52 119.71,41.52 119.57,41.38 119.2,41.38 119.06,41.52 118.41,41.52 117.4,42.53 116.87,42.53 116.47,42.92 116.47,43.46 116.25,43.67 115.72,43.67 115.32,44.07 115.32,44.6 115.1,44.82 114.57,44.82 114.17,45.22 114.17,45.75 113.95,45.97 113.42,45.97 113.02,46.37 113.02,46.9 111.74,48.18 111.36,48.18 111.01,47.84 U1.133
MIPI_CSI0_RX_D3N: length 27.4
  TOP w0.127: U1.132 111.21,46.84 111.51,46.54 112.12,46.54 117.83,40.83 118.65,40.83 118.96,40.52 118.96,39.94 119.09,39.81 119.34,39.81 119.47,39.94 119.47,40.52 119.77,40.83 120.28,40.83 120.58,40.52 120.58,39.94 120.71,39.81 120.97,39.81 121.09,39.94 121.09,40.52 121.4,40.83 121.9,40.83 122.21,40.52 122.21,39.94 122.34,39.81 122.59,39.81 122.72,39.94 122.72,40.52 123.02,40.83 124.4,40.83 125.91,39.32 125.91,35.82 125.96,35.78 U11.89
MIPI_CSI0_RX_D3P: length 27.5
  TOP w0.127: U1.131 111.12,45.84 111.52,46.24 111.99,46.24 113.7,44.53 113.7,44.24 113.91,44.03 114.2,44.03 114.42,43.81 114.42,43.52 114.63,43.31 114.92,43.31 115.14,43.09 115.14,42.8 115.35,42.59 115.64,42.59 117.71,40.52 118.53,40.52 118.65,40.4 118.65,39.82 118.96,39.51 119.47,39.51 119.77,39.82 119.77,40.4 119.9,40.52 120.15,40.52 120.28,40.4 120.28,39.82 120.59,39.51 121.09,39.51 121.4,39.82 121.4,40.4 121.52,40.52 121.78,40.52 121.91,40.4 121.91,39.82 122.21,39.51 122.72,39.51 123.02,39.82 123.02,40.4 123.15,40.52 124.28,40.52 125.6,39.2 125.6,35.86 125.56,35.81 U11.90
MIPI_CSI1_RX_CLK0N: length 75.6
  TOP w0.127: U13.85 43.11,35.63 43.06,35.68 43.06,36.98 44.03,37.95 53.29,37.95 54.5,39.16 54.5,40.09 v1(54.72,40.32) ; v1(106.21,44.18) 106.02,44.18 105.89,44.31 105.89,44.49 106.02,44.63 106.43,44.63 106.65,44.41 106.65,43.72 106.31,43.38 U1.125
  L3 w0.127: v1(106.21,44.18) 106.12,44.27 106.12,44.45 106,44.58 105.45,44.58 105.17,44.3 105.17,43.42 104.44,42.69 87.09,42.69 86.94,42.54 86.31,42.54 86.16,42.69 85.46,42.69 85.32,42.54 84.68,42.54 84.53,42.69 83.84,42.69 83.69,42.54 83.06,42.54 82.91,42.69 82.21,42.69 82.06,42.54 81.43,42.54 81.28,42.69 80.59,42.69 80.44,42.54 79.81,42.54 79.66,42.69 78.96,42.69 78.81,42.54 78.18,42.54 78.03,42.69 77.34,42.69 77.19,42.54 76.55,42.54 76.41,42.69 75.71,42.69 75.56,42.54 74.93,42.54 74.78,42.69 74.09,42.69 73.94,42.54 73.3,42.54 73.15,42.69 72.46,42.69 72.31,42.54 71.68,42.54 71.53,42.69 70.83,42.69 70.69,42.54 70.05,42.54 69.9,42.69 69.21,42.69 69.06,42.54 68.43,42.54 68.28,42.69 67.58,42.69 67.43,42.54 66.8,42.54 66.65,42.69 65.96,42.69 65.81,42.54 65.17,42.54 65.03,42.69 55.64,42.69 54.51,41.56 54.51,40.53 54.72,40.32 v1(54.72,40.32)
MIPI_CSI1_RX_CLK0P: length 75.6
  TOP w0.127: v1(53.97,40.32) 54.19,40.09 54.19,39.29 53.17,38.26 43.91,38.26 42.75,37.11 42.75,35.65 42.71,35.6 U13.86 ; U1.126 107.31,43.35 106.97,43.69 106.97,44.52 106.56,44.93 106.2,44.93 v1(106,45.14)
  L3 w0.127: v1(106,45.14) 105.74,44.88 105.32,44.88 104.87,44.43 104.87,43.55 104.31,42.99 86.96,42.99 86.81,42.84 86.43,42.84 86.29,42.99 85.34,42.99 85.19,42.84 84.81,42.84 84.66,42.99 83.71,42.99 83.56,42.84 83.18,42.84 83.03,42.99 82.09,42.99 81.94,42.84 81.56,42.84 81.41,42.99 80.46,42.99 80.31,42.84 79.93,42.84 79.78,42.99 78.84,42.99 78.69,42.84 78.31,42.84 78.16,42.99 77.21,42.99 77.06,42.84 76.68,42.84 76.53,42.99 75.58,42.99 75.44,42.84 75.05,42.84 74.91,42.99 73.96,42.99 73.81,42.84 73.43,42.84 73.28,42.99 72.33,42.99 72.18,42.84 71.8,42.84 71.65,42.99 70.71,42.99 70.56,42.84 70.18,42.84 70.03,42.99 69.08,42.99 68.93,42.84 68.55,42.84 68.4,42.99 67.46,42.99 67.31,42.84 66.93,42.84 66.78,42.99 65.83,42.99 65.68,42.84 65.3,42.84 65.15,42.99 55.51,42.99 54.21,41.68 54.21,40.56 v1(53.97,40.32)
MIPI_CSI1_RX_D0N: length 75.6
  TOP w0.127: U1.129 111.06,43.84 111.41,44.18 111.78,44.18 v1(112,43.95) ; U13.81 44.71,35.58 44.66,35.63 44.66,36.19 44.94,36.47 55.48,36.47 57.86,38.85 57.86,40.11 v1(58.09,40.33)
  L3 w0.127: v1(58.09,40.33) 57.85,40.57 57.85,40.75 58.04,40.94 60.16,40.94 60.33,40.78 60.83,40.78 61,40.94 61.51,40.94 61.67,40.78 62.18,40.78 62.35,40.94 62.85,40.94 63.02,40.78 63.53,40.78 63.69,40.94 106.45,40.94 109.69,44.18 111.78,44.18 v1(112,43.95)
MIPI_CSI1_RX_D0P: length 75.7
  TOP w0.127: U13.82 44.31,35.58 44.35,35.63 44.35,36.31 44.81,36.77 55.35,36.77 57.56,38.98 57.56,40.11 v1(57.33,40.33) ; U1.130 111.06,44.84 111.41,44.48 111.78,44.48 v1(112,44.71)
  L3 w0.127: v1(112,44.71) 111.78,44.48 109.56,44.48 106.32,41.25 57.92,41.25 57.55,40.88 57.55,40.55 v1(57.33,40.33)
MIPI_CSI1_RX_D1N: length 75.8
  TOP w0.127: U13.83 43.91,35.65 43.86,35.7 43.86,36.55 44.55,37.24 54.45,37.24 54.62,37.41 54.89,37.41 55.11,37.63 55.11,37.9 55.34,38.12 55.61,38.12 55.83,38.35 55.83,38.62 56.22,39.01 56.22,40.1 v1(56.45,40.33) ; v1(108.17,44.23) 108.08,44.32 108.08,44.5 108.21,44.63 108.45,44.63 108.68,44.4 108.68,43.95 108.31,43.58 U1.127
  L3 w0.127: v1(56.45,40.33) 56.22,40.55 56.22,41.14 56.81,41.73 87.82,41.73 87.95,41.86 88.68,41.86 88.81,41.73 89.45,41.73 89.58,41.86 90.31,41.86 90.44,41.73 91.07,41.73 91.2,41.86 91.94,41.86 92.06,41.73 92.7,41.73 92.83,41.86 93.56,41.86 93.69,41.73 94.32,41.73 94.45,41.86 95.19,41.86 95.32,41.73 95.95,41.73 96.08,41.86 96.81,41.86 96.94,41.73 97.57,41.73 97.7,41.86 98.44,41.86 98.57,41.73 99.2,41.73 99.33,41.86 100.06,41.86 100.19,41.73 100.83,41.73 100.95,41.86 101.69,41.86 101.82,41.73 102.45,41.73 102.58,41.86 103.32,41.86 103.44,41.73 105.53,41.73 107.18,43.38 107.18,44.29 107.52,44.64 108.04,44.64 108.17,44.51 v1(108.17,44.23)
MIPI_CSI1_RX_D1P: length 75.9
  TOP w0.127: v1(107.99,45.16) 108.21,44.94 108.56,44.94 108.98,44.53 108.98,43.95 109.31,43.58 U1.128 ; U13.84 43.51,35.64 43.55,35.69 43.55,36.68 44.42,37.54 54.32,37.54 55.91,39.13 55.91,40.1 v1(55.69,40.33)
  L3 w0.127: v1(55.69,40.33) 55.91,40.55 55.91,41.26 56.69,42.04 87.69,42.04 87.82,42.17 88.81,42.17 88.94,42.04 89.32,42.04 89.45,42.17 90.44,42.17 90.57,42.04 90.95,42.04 91.07,42.17 92.06,42.17 92.19,42.04 92.57,42.04 92.7,42.17 93.69,42.17 93.82,42.04 94.2,42.04 94.33,42.17 95.31,42.17 95.44,42.04 95.82,42.04 95.95,42.17 96.94,42.17 97.07,42.04 97.45,42.04 97.58,42.17 98.56,42.17 98.69,42.04 99.07,42.04 99.2,42.17 100.19,42.17 100.32,42.04 100.7,42.04 100.83,42.17 101.82,42.17 101.94,42.04 102.33,42.04 102.45,42.17 103.44,42.17 103.57,42.04 105.4,42.04 106.87,43.51 106.87,44.42 107.4,44.94 107.78,44.94 v1(107.99,45.16)
MIPI_CSI1_RX_D2N: length 75.7
  TOP w0.127: U13.87 42.31,35.58 42.26,35.63 42.26,37.39 42.85,37.98 43.03,37.98 43.3,38.25 43.3,38.43 43.58,38.71 52.15,38.71 52.79,39.35 52.79,40.07 v1(53.01,40.3) ; v1(104.17,44.1) 104.13,44.1 104.02,44.21 104.02,44.39 104.14,44.52 104.56,44.52 104.71,44.38 104.71,43.76 104.31,43.36 U1.123
  L3 w0.127: v1(104.17,44.1) 104.17,44.36 103.97,44.56 103.49,44.56 103.19,44.26 103.19,43.84 102.85,43.5 97.99,43.5 97.74,43.75 97.36,43.75 97.11,43.5 96.37,43.5 96.11,43.75 95.73,43.75 95.48,43.5 94.74,43.5 94.49,43.75 94.11,43.75 93.85,43.5 93.12,43.5 92.86,43.75 92.48,43.75 92.23,43.5 91.49,43.5 91.24,43.75 90.86,43.75 90.6,43.5 89.86,43.5 89.61,43.75 89.23,43.75 88.98,43.5 88.24,43.5 87.99,43.75 87.61,43.75 87.35,43.5 86.61,43.5 86.36,43.75 85.98,43.75 85.73,43.5 83.39,43.5 83.18,43.71 82.8,43.71 82.59,43.5 81.77,43.5 81.56,43.71 81.17,43.71 80.96,43.5 80.14,43.5 79.93,43.71 79.55,43.71 79.34,43.5 78.52,43.5 78.3,43.71 77.92,43.71 77.71,43.5 76.89,43.5 76.68,43.71 76.3,43.71 76.09,43.5 75.26,43.5 75.05,43.71 74.67,43.71 74.46,43.5 73.64,43.5 73.43,43.71 73.05,43.71 72.83,43.5 72.01,43.5 71.8,43.71 71.42,43.71 71.21,43.5 70.39,43.5 70.18,43.71 69.8,43.71 69.58,43.5 54.65,43.5 52.79,41.64 52.79,40.52 v1(53.01,40.3)
MIPI_CSI1_RX_D2P: length 75.9
  TOP w0.127: v1(52.25,40.3) 52.48,40.07 52.48,39.47 52.02,39.01 43.45,39.01 41.95,37.52 41.95,35.65 41.91,35.6 U13.88 ; U1.124 105.31,43.44 105.01,43.73 105.01,44.5 104.66,44.86 104.27,44.86 v1(104.04,45.08)
  L3 w0.127: v1(52.25,40.3) 52.48,40.52 52.48,41.76 54.52,43.8 69.46,43.8 69.67,44.02 70.3,44.02 70.51,43.8 71.08,43.8 71.29,44.02 71.93,44.02 72.14,43.8 72.71,43.8 72.92,44.02 73.55,44.02 73.77,43.8 74.33,43.8 74.55,44.02 75.18,44.02 75.39,43.8 75.96,43.8 76.17,44.02 76.8,44.02 77.02,43.8 77.59,43.8 77.8,44.02 78.43,44.02 78.64,43.8 79.21,43.8 79.42,44.02 80.06,44.02 80.27,43.8 80.84,43.8 81.05,44.02 81.68,44.02 81.89,43.8 82.46,43.8 82.67,44.02 83.31,44.02 83.52,43.8 85.6,43.8 85.85,44.06 86.49,44.06 86.74,43.8 87.23,43.8 87.48,44.06 88.11,44.06 88.37,43.8 88.85,43.8 89.1,44.06 89.74,44.06 89.99,43.8 90.48,43.8 90.73,44.06 91.36,44.06 91.62,43.8 92.1,43.8 92.36,44.06 92.99,44.06 93.24,43.8 93.73,43.8 93.98,44.06 94.62,44.06 94.87,43.8 95.35,43.8 95.61,44.06 96.24,44.06 96.49,43.8 96.98,43.8 97.23,44.06 97.87,44.06 98.12,43.8 102.73,43.8 102.89,43.96 102.89,44.39 103.36,44.87 103.82,44.87 v1(104.04,45.08)
MIPI_CSI1_RX_D3N: length 75.6
  TOP w0.127: v1(51.44,40.29) 51.25,40.1 51.25,39.75 50.94,39.44 50.69,39.44 43.14,39.44 41.46,37.76 41.46,35.64 41.51,35.59 U13.89 ; v1(102.07,44.41) 102.2,44.54 102.54,44.54 102.67,44.41 102.67,43.65 102.31,43.29 U1.121
  L3 w0.127: v1(102.07,44.41) 101.94,44.54 100.93,44.54 100.68,44.29 100.09,44.29 99.84,44.54 99.33,44.54 99.14,44.34 98.44,44.34 98.24,44.54 69.29,44.54 68.99,44.85 68.99,44.96 68.86,45.09 68.61,45.09 68.48,44.96 68.48,44.85 68.18,44.54 67.67,44.54 67.36,44.85 67.36,44.96 67.24,45.09 66.98,45.09 66.86,44.96 66.86,44.85 66.55,44.54 66.04,44.54 65.74,44.85 65.74,44.96 65.61,45.09 65.36,45.09 65.23,44.96 65.23,44.85 64.92,44.54 64.42,44.54 64.11,44.85 64.11,44.96 63.99,45.09 63.73,45.09 63.6,44.96 63.6,44.85 63.3,44.54 62.79,44.54 62.49,44.85 62.49,44.96 62.36,45.09 62.11,45.09 61.98,44.96 61.98,44.85 61.67,44.54 61.17,44.54 60.86,44.85 60.86,44.96 60.73,45.09 60.48,45.09 60.35,44.96 60.35,44.85 60.05,44.54 59.54,44.54 59.24,44.85 59.24,44.96 59.11,45.09 58.85,45.09 58.73,44.96 58.73,44.85 58.42,44.54 57.18,44.54 57.01,44.37 56.5,44.37 56.32,44.54 55.82,44.54 55.64,44.37 55.13,44.37 54.95,44.54 53.78,44.54 53.28,44.04 53.28,43.86 53.3,43.84 53.3,43.66 53.12,43.48 52.94,43.48 52.92,43.5 52.74,43.5 52.56,43.32 52.56,43.14 52.58,43.12 52.58,42.94 52.4,42.76 52.23,42.76 52.2,42.78 52.02,42.78 51.25,42.01 51.25,40.47 v1(51.44,40.29)
MIPI_CSI1_RX_D3P: length 75.7
  TOP w0.127: v1(50.72,40.28) 50.94,40.06 50.94,39.87 50.82,39.75 43.01,39.75 41.15,37.89 41.15,35.63 41.11,35.58 U13.90 ; v1(102.07,45.07) 102.29,44.85 102.67,44.85 102.98,44.53 102.98,43.62 103.31,43.3 U1.122
  L3 w0.127: v1(102.07,45.07) 101.84,44.85 100.8,44.85 100.55,44.6 100.22,44.6 99.97,44.85 69.42,44.85 69.29,44.97 69.29,45.09 68.99,45.4 68.48,45.4 68.18,45.09 68.18,44.97 68.05,44.85 67.8,44.85 67.67,44.97 67.67,45.09 67.36,45.4 66.86,45.4 66.55,45.09 66.55,44.97 66.42,44.85 66.17,44.85 66.04,44.97 66.04,45.09 65.74,45.4 65.23,45.4 64.93,45.09 64.93,44.97 64.8,44.85 64.54,44.85 64.42,44.97 64.42,45.09 64.11,45.4 63.61,45.4 63.3,45.09 63.3,44.97 63.17,44.85 62.92,44.85 62.79,44.97 62.79,45.09 62.49,45.4 61.98,45.4 61.67,45.09 61.67,44.97 61.55,44.85 61.29,44.85 61.17,44.97 61.17,45.09 60.86,45.4 60.35,45.4 60.05,45.09 60.05,44.97 59.92,44.85 59.67,44.85 59.54,44.97 59.54,45.09 59.23,45.4 58.73,45.4 58.42,45.09 58.42,44.97 58.3,44.85 53.65,44.85 50.95,42.14 50.95,40.51 v1(50.72,40.28)
OSC_IN: length 8.2
  TOP w0.203: X2.1 114.9,23.98 114.16,23.98 R38.1 113.55,24.02 113.26,24.02 C63.1 112.53,24.01 112.24,24.01 112.03,23.81 112.03,22.62 111.45,22.03 U8.5
OSC_OUT: length 8.2
  TOP w0.203: U8.6 111.37,22.53 111.67,22.83 111.67,24.01 112.07,24.41 112.54,24.41 C64.1 113.27,24.37 113.56,24.37 R38.2 114.22,24.35 114.84,24.35 X2.2
OUTPUT1: length 131.7
  TOP w0.127: v1(20.86,123.93) ED23.1 20.29,125.2 19.32,126.17 U24.L1
  BOTTOM w0.127: Q22.3 66.73,23.3 R286.1 66.29,25.37 66.25,25.33 65.24,25.33 64.62,25.95 64.23,25.95 60.15,30.03 60.15,47.72 52.35,55.52 44.51,55.52 37,63.03 37,104.94 20.86,121.09 v1(20.86,123.93)
OUTPUT2: length 148.7
  TOP w0.127: v1(22.08,123.93) ED24.1 21.51,125.18 20.59,126.1 20.59,132.01 U24.L2
  BOTTOM w0.127: R287.1 78.77,23.48 Q23.3 77.09,23.47 76.56,24 76.56,24.88 75.36,26.08 64.85,26.08 64.73,26.21 64.58,26.21 60.42,30.37 60.42,47.86 52.5,55.77 52.46,55.77 52.45,55.77 44.65,55.77 37.41,63.01 37.41,105.04 22.08,120.37 v1(22.08,123.93)
OUTPUT3: length 134.4
  TOP w0.127: U24.L3 21.08,135.51 21.08,126.82 22.72,125.18 ED25.1 v1(23.29,123.94)
  BOTTOM w0.127: Q24.3 66.68,28.51 R288.1 64.96,30.71 60.76,34.9 60.76,47.87 52.61,56.02 52.56,56.02 52.56,56.02 44.82,56.02 37.82,63.03 37.82,105.15 23.29,119.68 v1(23.29,123.94)
OUTPUT4: length 151.3
  TOP w0.102: U24.L4 19.32,140.08
  TOP w0.127: v1(24.51,123.94) ED26.1 23.95,125.12 21.61,127.45 21.61,137.79 19.32,140.08
  BOTTOM w0.127: 78.8,30.76 77.61,29.57 76.3,29.57 75.6,30.26 71.74,30.26 70.59,31.41 64.86,31.41 61.1,35.17 61.1,47.98 52.8,56.28 52.66,56.28 44.94,56.28 38.23,62.99 38.23,105.26 24.51,118.97 v1(24.51,123.94) ; 78.8,30.76 R289.1 ; 78.8,30.76 78.83,30.73 Q25.3
PCIE20_0_RXN/SATA30_0_RXN: length 87.1
  TOP w0.127: v1(113.12,98.71) 112.89,98.49 111.55,98.49 111.2,98.84 U1.184
  L3 w0.127: v1(113.12,98.71) 112.89,98.49 112.46,98.49 112.16,98.19 112.16,97.66 114.29,95.53 114.29,80.28 116.03,78.55 116.03,64.91 119.64,61.3 136.06,61.3 142.85,54.51 152.24,54.51 v1(152.32,54.43)
  BOTTOM w0.127: v1(152.32,54.43) 152.41,54.51 156.06,54.51 156.78,55.23 156.78,56.64 156.33,57.08 155.92,57.08 155.78,57.23 C357.1
PCIE20_0_RXP/SATA30_0_RXP: length 87.2
  TOP w0.127: U1.183 111.19,97.84 111.54,98.18 112.89,98.18 v1(113.12,97.96)
  L3 w0.127: v1(152.32,54.91) 152.23,54.81 142.97,54.81 136.19,61.6 119.76,61.6 116.33,65.03 116.33,78.68 114.6,80.41 114.6,84.58 114.73,84.7 114.73,84.7 114.86,84.83 114.86,85.09 114.73,85.21 114.73,85.21 114.6,85.34 114.6,85.59 114.73,85.72 114.73,85.72 114.86,85.85 114.86,86.1 114.73,86.23 114.73,86.23 114.6,86.36 114.6,86.61 114.73,86.74 114.73,86.74 114.86,86.86 114.86,87.12 114.73,87.24 114.73,87.24 114.6,87.37 114.6,87.63 114.73,87.75 114.73,87.75 114.86,87.88 114.86,88.13 114.73,88.26 114.73,88.26 114.6,88.39 114.6,88.64 114.75,88.8 114.75,89.15 114.6,89.3 114.6,89.66 114.75,89.81 114.75,90.17 114.6,90.32 114.6,90.67 114.75,90.83 114.75,91.18 114.6,91.34 114.6,91.69 114.75,91.84 114.75,92.2 114.6,92.35 114.6,92.71 114.75,92.86 114.75,93.21 114.6,93.37 114.6,93.72 114.75,93.88 114.75,94.23 114.6,94.38 114.6,94.74 114.75,94.89 114.75,95.25 114.6,95.4 114.6,95.65 114.36,95.9 114.36,96.19 114.14,96.4 113.85,96.4 113.64,96.62 113.64,96.91 113.43,97.12 113.13,97.12 112.46,97.79 112.46,98.06 112.59,98.19 112.89,98.19 v1(113.12,97.96)
  BOTTOM w0.127: C358.1 155.92,56.78 156.21,56.78 156.47,56.51 156.47,55.35 155.93,54.81 152.42,54.81 v1(152.32,54.91)
PCIE20_0_TXN/SATA30_0_TXN: length 91.6
  TOP w0.127: U1.181 110.95,95.84 111.24,96.12 111.55,96.12 v1(111.77,95.91)
  L3 w0.127: v1(111.77,95.91) 111.51,96.17 111.11,96.17 110.98,96.04 110.98,76.91 114.76,73.13 114.76,64.66 119.34,60.09 135.98,60.09 142.67,53.39 144.11,53.39 144.33,53.61 144.62,53.61 144.84,53.39 145.13,53.39 145.34,53.61 145.64,53.61 145.85,53.39 146.14,53.39 146.36,53.61 146.65,53.61 146.87,53.39 147.16,53.39 147.38,53.61 147.67,53.61 147.88,53.39 148.18,53.39 148.39,53.61 148.68,53.61 148.9,53.39 149.19,53.39 149.41,53.61 149.7,53.61 149.92,53.39 150.21,53.39 150.42,53.61 150.72,53.61 150.93,53.39 151.22,53.39 151.44,53.61 151.73,53.61 151.95,53.39 152.24,53.39 v1(152.32,53.47)
  BOTTOM w0.127: C355.1 154.17,57.65 156.87,57.65 157.36,57.17 157.36,54.33 156.42,53.39 155.51,53.39 155.29,53.61 155,53.61 154.78,53.39 154.49,53.39 154.27,53.61 153.98,53.61 153.76,53.39 153.48,53.39 153.26,53.61 152.97,53.61 152.75,53.39 152.39,53.39 v1(152.32,53.47)
PCIE20_0_TXP/SATA30_0_TXP: length 91.7
  TOP w0.127: U1.182 110.93,96.84 111.25,96.51 111.62,96.51 v1(111.77,96.66)
  L3 w0.127: v1(152.32,52.99) 152.21,53.09 142.55,53.09 135.86,59.78 119.21,59.78 114.46,64.54 114.46,73.01 110.67,76.79 110.67,96.17 110.98,96.47 111.58,96.47 v1(111.77,96.66)
  BOTTOM w0.127: v1(152.32,52.99) 152.41,53.09 156.55,53.09 157.66,54.2 157.66,57.3 157,57.96 154.17,57.96 C356.1
PCIE20_2_REFCLKN: length 140.2
  TOP w0.127: U1.189 110.89,103.84 111.25,104.19 111.63,104.19 v1(111.85,103.97)
  L3 w0.127: v1(35.46,41.26) 35.68,41.49 35.68,41.93 36.3,42.55 36.65,42.55 37.16,43.05 37.16,43.33 37.38,43.55 37.65,43.55 37.87,43.77 37.87,44.05 38.09,44.27 38.37,44.27 38.59,44.49 38.59,44.77 38.81,44.99 39.09,44.99 41.68,47.58 42.11,47.58 42.71,46.98 42.89,46.98 43.07,47.16 43.07,47.34 42.47,47.94 42.47,48.37 42.83,48.73 43.26,48.73 43.86,48.13 44.04,48.13 44.22,48.31 44.22,48.49 43.62,49.09 43.62,49.52 43.98,49.88 44.41,49.88 45.01,49.28 45.19,49.28 45.37,49.46 45.37,49.64 44.77,50.24 44.77,50.67 45.18,51.08 46.49,51.08 46.8,50.77 46.8,49.94 46.92,49.81 47.18,49.81 47.3,49.94 47.3,50.77 47.61,51.08 55.19,51.08 56.67,49.59 87.64,49.59 97.04,58.99 106.69,58.99 109.75,62.06 109.75,100.21 112.39,102.84 112.39,104.07 112.26,104.2 112.08,104.2 v1(111.85,103.97)
  BOTTOM w0.127: v1(35.46,41.26) 35.67,41.05 35.67,40.45 35.55,40.34 J2.53
PCIE20_2_REFCLKP: length 140.3
  TOP w0.127: v1(111.85,104.72) 111.62,104.49 111.23,104.49 110.89,104.84 U1.190
  L3 w0.127: v1(36.21,41.26) 35.99,41.49 35.99,41.8 36.43,42.24 36.77,42.24 41.81,47.28 41.99,47.28 42.59,46.68 43.02,46.68 43.38,47.03 43.38,47.47 42.78,48.07 42.78,48.25 42.96,48.43 43.14,48.43 43.74,47.83 44.17,47.83 44.53,48.18 44.53,48.62 43.93,49.22 43.93,49.4 44.11,49.58 44.29,49.58 44.89,48.98 45.32,48.98 45.68,49.33 45.68,49.77 45.08,50.37 45.08,50.55 45.3,50.77 46.36,50.77 46.49,50.64 46.49,49.81 46.8,49.51 47.3,49.51 47.61,49.81 47.61,50.64 47.73,50.77 55.06,50.77 56.54,49.29 87.77,49.29 97.17,58.69 106.81,58.69 110.06,61.93 110.06,100.08 112.69,102.72 112.69,104.2 112.39,104.5 112.07,104.5 v1(111.85,104.72)
  BOTTOM w0.127: J2.55 36.05,40.4 35.97,40.49 35.97,41.02 v1(36.21,41.26)
PCIE20_2_RXN/SATA30_2_RXN: length 140.1
  TOP w0.127: U1.185 109.17,99.84 108.86,100.14 107.23,100.14 v1(107,99.92)
  L3 w0.127: v1(32.43,41.28) 32.65,41.5 32.65,42.38 42.7,52.43 43.35,52.43 44.07,53.15 44.49,53.15 44.62,53.28 44.62,54.02 44.93,54.33 45.43,54.33 45.74,54.02 45.74,53.28 45.86,53.15 46.12,53.15 46.25,53.28 46.25,54.02 46.55,54.33 47.06,54.33 47.36,54.02 47.36,53.28 47.49,53.15 47.74,53.15 47.87,53.28 47.87,54.02 48.18,54.33 48.68,54.33 48.99,54.02 48.99,53.28 49.12,53.15 49.37,53.15 49.5,53.28 49.5,54.02 49.8,54.33 50.31,54.33 50.61,54.02 50.61,53.28 50.74,53.15 51,53.15 51.12,53.28 51.12,54.02 51.43,54.33 51.93,54.33 52.24,54.02 52.24,53.28 52.37,53.15 52.62,53.15 52.75,53.28 52.75,53.85 53.05,54.15 53.56,54.15 53.87,53.85 53.87,53.28 53.99,53.15 56.56,53.15 57.72,52 86.07,52 94.94,60.86 105.97,60.86 107.51,62.39 107.51,95.39 107.34,95.55 107.34,95.9 107.51,96.06 107.51,96.4 107.34,96.57 107.34,96.91 107.51,97.08 107.51,97.42 107.34,97.59 107.34,97.93 107.51,98.09 107.51,98.44 107.34,98.6 107.34,98.94 107.51,99.11 107.51,100.02 107.38,100.14 107.23,100.14 v1(107,99.92)
  BOTTOM w0.127: J2.41 32.55,40.42 32.65,40.52 32.65,41.05 v1(32.43,41.28)
